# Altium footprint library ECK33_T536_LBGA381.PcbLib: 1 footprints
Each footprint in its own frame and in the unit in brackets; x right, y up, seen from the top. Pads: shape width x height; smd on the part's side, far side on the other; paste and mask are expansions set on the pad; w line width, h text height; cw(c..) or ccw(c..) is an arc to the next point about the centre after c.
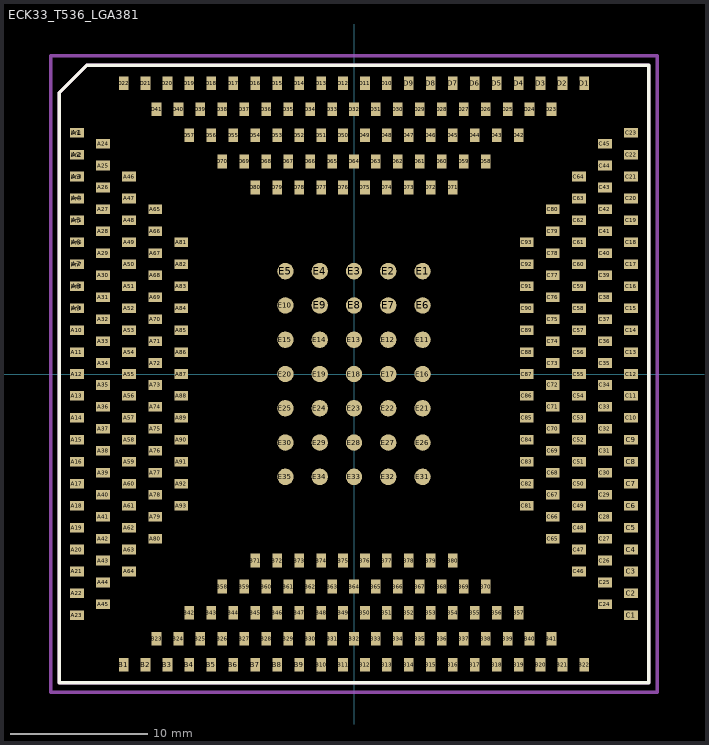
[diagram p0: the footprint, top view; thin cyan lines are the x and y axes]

## ECK33_T536_LGA381 [mm]
pads (727):
  rect 1x0.7 smd: A1(-20.2,17.6) A2(-20.2,16) A3(-20.2,14.4) A4(-20.2,12.8) A5(-20.2,11.2) A6(-20.2,9.6) A7(-20.2,8) A8(-20.2,6.4) A9(-20.2,4.8) A10(-20.2,3.2) A11(-20.2,1.6) A12(-20.2,0) A13(-20.2,-1.6) A14(-20.2,-3.2) A15(-20.2,-4.8) A16(-20.2,-6.4) A17(-20.2,-8) A18(-20.2,-9.6) A19(-20.2,-11.2) A20(-20.2,-12.8) A21(-20.2,-14.4) A22(-20.2,-16) A23(-20.2,-17.6) A24(-18.3,16.8) A25(-18.3,15.2) A26(-18.3,13.6) A27(-18.3,12) A28(-18.3,10.4) A29(-18.3,8.8) A30(-18.3,7.2) A31(-18.3,5.6) A32(-18.3,4) A33(-18.3,2.4) A34(-18.3,0.8) A35(-18.3,-0.8) A36(-18.3,-2.4) A37(-18.3,-4) A38(-18.3,-5.6) A39(-18.3,-7.2) A40(-18.3,-8.8) A41(-18.3,-10.4) A42(-18.3,-12) A43(-18.3,-13.6) A44(-18.3,-15.2) A45(-18.3,-16.8) A46(-16.4,14.4) A47(-16.4,12.8) A48(-16.4,11.2) A49(-16.4,9.6) A50(-16.4,8) A51(-16.4,6.4) A52(-16.4,4.8) A53(-16.4,3.2) A54(-16.4,1.6) A55(-16.4,0) A56(-16.4,-1.6) A57(-16.4,-3.2) A58(-16.4,-4.8) A59(-16.4,-6.4) A60(-16.4,-8) A61(-16.4,-9.6) A62(-16.4,-11.2) A63(-16.4,-12.8) A64(-16.4,-14.4) A65(-14.5,12) A66(-14.5,10.4) A67(-14.5,8.8) A68(-14.5,7.2) A69(-14.5,5.6) A70(-14.5,4) A71(-14.5,2.4) A72(-14.5,0.8) A73(-14.5,-0.8) A74(-14.5,-2.4) A75(-14.5,-4) A76(-14.5,-5.6) A77(-14.5,-7.2) A78(-14.5,-8.8) A79(-14.5,-10.4) A80(-14.5,-12) A81(-12.6,9.6) A82(-12.6,8) A83(-12.6,6.4) A84(-12.6,4.8) A85(-12.6,3.2) A86(-12.6,1.6) A87(-12.6,0) A88(-12.6,-1.6) A89(-12.6,-3.2) A90(-12.6,-4.8) A91(-12.6,-6.4) A92(-12.6,-8) A93(-12.6,-9.6) C1(20.2,-17.6) C2(20.2,-16) C3(20.2,-14.4) C4(20.2,-12.8) C5(20.2,-11.2) C6(20.2,-9.6) C7(20.2,-8) C8(20.2,-6.4) C9(20.2,-4.8) C10(20.2,-3.2) C11(20.2,-1.6) C12(20.2,0) C13(20.2,1.6) C14(20.2,3.2) C15(20.2,4.8) C16(20.2,6.4) C17(20.2,8) C18(20.2,9.6) C19(20.2,11.2) C20(20.2,12.8) C21(20.2,14.4) C22(20.2,16) C23(20.2,17.6) C24(18.3,-16.8) C25(18.3,-15.2) C26(18.3,-13.6) C27(18.3,-12) C28(18.3,-10.4) C29(18.3,-8.8) C30(18.3,-7.2) C31(18.3,-5.6) C32(18.3,-4) C33(18.3,-2.4) C34(18.3,-0.8) C35(18.3,0.8) C36(18.3,2.4) C37(18.3,4) C38(18.3,5.6) C39(18.3,7.2) C40(18.3,8.8) C41(18.3,10.4) C42(18.3,12) C43(18.3,13.6) C44(18.3,15.2) C45(18.3,16.8) C46(16.4,-14.4) C47(16.4,-12.8) C48(16.4,-11.2) C49(16.4,-9.6) C50(16.4,-8) C51(16.4,-6.4) C52(16.4,-4.8) C53(16.4,-3.2) C54(16.4,-1.6) C55(16.4,0) C56(16.4,1.6) C57(16.4,3.2) C58(16.4,4.8) C59(16.4,6.4) C60(16.4,8) C61(16.4,9.6) C62(16.4,11.2) C63(16.4,12.8) C64(16.4,14.4) C65(14.5,-12) C66(14.5,-10.4) C67(14.5,-8.8) C68(14.5,-7.2) C69(14.5,-5.6) C70(14.5,-4) C71(14.5,-2.4) C72(14.5,-0.8) C73(14.5,0.8) C74(14.5,2.4) C75(14.5,4) C76(14.5,5.6) C77(14.5,7.2) C78(14.5,8.8) C79(14.5,10.4) C80(14.5,12) C81(12.6,-9.6) C82(12.6,-8) C83(12.6,-6.4) C84(12.6,-4.8) C85(12.6,-3.2) C86(12.6,-1.6) C87(12.6,0) C88(12.6,1.6) C89(12.6,3.2) C90(12.6,4.8) C91(12.6,6.4) C92(12.6,8) C93(12.6,9.6)
  rect 0.7x1 smd: B1(-16.8,-21.2) B2(-15.2,-21.2) B3(-13.6,-21.2) B4(-12,-21.2) B5(-10.4,-21.2) B6(-8.8,-21.2) B7(-7.2,-21.2) B8(-5.6,-21.2) B9(-4,-21.2) B10(-2.4,-21.2) B11(-0.8,-21.2) B12(0.8,-21.2) B13(2.4,-21.2) B14(4,-21.2) B15(5.6,-21.2) B16(7.2,-21.2) B17(8.8,-21.2) B18(10.4,-21.2) B19(12,-21.2) B20(13.6,-21.2) B21(15.2,-21.2) B22(16.8,-21.2) B23(-14.4,-19.3) B24(-12.8,-19.3) B25(-11.2,-19.3) B26(-9.6,-19.3) B27(-8,-19.3) B28(-6.4,-19.3) B29(-4.8,-19.3) B30(-3.2,-19.3) B31(-1.6,-19.3) B32(0,-19.3) B33(1.6,-19.3) B34(3.2,-19.3) B35(4.8,-19.3) B36(6.4,-19.3) B37(8,-19.3) B38(9.6,-19.3) B39(11.2,-19.3) B40(12.8,-19.3) B41(14.4,-19.3) B42(-12,-17.4) B43(-10.4,-17.4) B44(-8.8,-17.4) B45(-7.2,-17.4) B46(-5.6,-17.4) B47(-4,-17.4) B48(-2.4,-17.4) B49(-0.8,-17.4) B50(0.8,-17.4) B51(2.4,-17.4) B52(4,-17.4) B53(5.6,-17.4) B54(7.2,-17.4) B55(8.8,-17.4) B56(10.4,-17.4) B57(12,-17.4) B58(-9.6,-15.5) B59(-8,-15.5) B60(-6.4,-15.5) B61(-4.8,-15.5) B62(-3.2,-15.5) B63(-1.6,-15.5) B64(0,-15.5) B65(1.6,-15.5) B66(3.2,-15.5) B67(4.8,-15.5) B68(6.4,-15.5) B69(8,-15.5) B70(9.6,-15.5) B71(-7.2,-13.6) B72(-5.6,-13.6) B73(-4,-13.6) B74(-2.4,-13.6) B75(-0.8,-13.6) B76(0.8,-13.6) B77(2.4,-13.6) B78(4,-13.6) B79(5.6,-13.6) B80(7.2,-13.6) D1(16.8,21.2) D2(15.2,21.2) D3(13.6,21.2) D4(12,21.2) D5(10.4,21.2) D6(8.8,21.2) D7(7.2,21.2) D8(5.6,21.2) D9(4,21.2) D10(2.4,21.2) D11(0.8,21.2) D12(-0.8,21.2) D13(-2.4,21.2) D14(-4,21.2) D15(-5.6,21.2) D16(-7.2,21.2) D17(-8.8,21.2) D18(-10.4,21.2) D19(-12,21.2) D20(-13.6,21.2) D21(-15.2,21.2) D22(-16.8,21.2) D23(14.4,19.3) D24(12.8,19.3) D25(11.2,19.3) D26(9.6,19.3) D27(8,19.3) D28(6.4,19.3) D29(4.8,19.3) D30(3.2,19.3) D31(1.6,19.3) D32(0,19.3) D33(-1.6,19.3) D34(-3.2,19.3) D35(-4.8,19.3) D36(-6.4,19.3) D37(-8,19.3) D38(-9.6,19.3) D39(-11.2,19.3) D40(-12.8,19.3) D41(-14.4,19.3) D42(12,17.4) D43(10.4,17.4) D44(8.8,17.4) D45(7.2,17.4) D46(5.6,17.4) D47(4,17.4) D48(2.4,17.4) D49(0.8,17.4) D50(-0.8,17.4) D51(-2.4,17.4) D52(-4,17.4) D53(-5.6,17.4) D54(-7.2,17.4) D55(-8.8,17.4) D56(-10.4,17.4) D57(-12,17.4) D58(9.6,15.5) D59(8,15.5) D60(6.4,15.5) D61(4.8,15.5) D62(3.2,15.5) D63(1.6,15.5) D64(0,15.5) D65(-1.6,15.5) D66(-3.2,15.5) D67(-4.8,15.5) D68(-6.4,15.5) D69(-8,15.5) D70(-9.6,15.5) D71(7.2,13.6) D72(5.6,13.6) D73(4,13.6) D74(2.4,13.6) D75(0.8,13.6) D76(-0.8,13.6) D77(-2.4,13.6) D78(-4,13.6) D79(-5.6,13.6) D80(-7.2,13.6)
  round 1.2 smd: E1(5,7.5) E2(2.5,7.5) E3(0,7.5) E4(-2.5,7.5) E5(-5,7.5) E6(5,5) E7(2.5,5) E8(0,5) E9(-2.5,5) E10(-5,5) E11(5,2.5) E12(2.5,2.5) E13(0,2.5) E14(-2.5,2.5) E15(-5,2.5) E16(5,0) E17(2.5,0) E18(0,0) E19(-2.5,0) E20(-5,0) E21(5,-2.5) E22(2.5,-2.5) E23(0,-2.5) E24(-2.5,-2.5) E25(-5,-2.5) E26(5,-5) E27(2.5,-5) E28(0,-5) E29(-2.5,-5) E30(-5,-5) E31(5,-7.5) E32(2.5,-7.5) E33(0,-7.5) E34(-2.5,-7.5) E35(-5,-7.5)
  rrect25% 1x0.7 on Top Paste: Un1(-20.2,17.6) Un2(-20.2,16) Un3(-20.2,14.4) Un4(-20.2,12.8) Un5(-20.2,11.2) Un6(-20.2,9.6) Un7(-20.2,8) Un8(-20.2,6.4) Un9(-20.2,4.8) Un10(-20.2,3.2) Un11(-20.2,1.6) Un12(-20.2,0) Un13(-20.2,-1.6) Un14(-20.2,-3.2) Un15(-20.2,-4.8) Un16(-20.2,-6.4) Un17(-20.2,-8) Un18(-20.2,-9.6) Un19(-20.2,-11.2) Un20(-20.2,-12.8) Un21(-20.2,-14.4) Un22(-20.2,-16) Un23(-20.2,-17.6) Un24(-18.3,16.8) Un25(-18.3,15.2) Un26(-18.3,13.6) Un27(-18.3,12) Un28(-18.3,10.4) Un29(-18.3,8.8) Un30(-18.3,7.2) Un31(-18.3,5.6) Un32(-18.3,4) Un33(-18.3,2.4) Un34(-18.3,0.8) Un35(-18.3,-0.8) Un36(-18.3,-2.4) Un37(-18.3,-4) Un38(-18.3,-5.6) Un39(-18.3,-7.2) Un40(-18.3,-8.8) Un41(-18.3,-10.4) Un42(-18.3,-12) Un43(-18.3,-13.6) Un44(-18.3,-15.2) Un45(-18.3,-16.8) Un48(-16.4,14.4) Un49(-16.4,12.8) Un50(-16.4,11.2) Un51(-16.4,9.6) Un52(-16.4,8) Un53(-16.4,6.4) Un54(-16.4,4.8) Un55(-16.4,3.2) Un56(-16.4,1.6) Un57(-16.4,0) Un58(-16.4,-1.6) Un59(-16.4,-3.2) Un60(-16.4,-4.8) Un61(-16.4,-6.4) Un62(-16.4,-8) Un63(-16.4,-9.6) Un64(-16.4,-11.2) Un65(-16.4,-12.8) Un66(-16.4,-14.4) Un69(-14.5,12) Un70(-14.5,10.4) Un71(-14.5,8.8) Un72(-14.5,7.2) Un73(-14.5,5.6) Un74(-14.5,4) Un75(-14.5,2.4) Un76(-14.5,0.8) Un77(-14.5,-0.8) Un78(-14.5,-2.4) Un79(-14.5,-4) Un80(-14.5,-5.6) Un81(-14.5,-7.2) Un82(-14.5,-8.8) Un83(-14.5,-10.4) Un84(-14.5,-12) Un91(-12.6,9.6) Un92(-12.6,8) Un93(-12.6,6.4) Un94(-12.6,4.8) Un95(-12.6,3.2) Un96(-12.6,1.6) Un97(-12.6,0) Un98(-12.6,-1.6) Un99(-12.6,-3.2) Un100(-12.6,-4.8) Un101(-12.6,-6.4) Un102(-12.6,-8) Un103(-12.6,-9.6) Un244(12.6,9.6) Un245(12.6,8) Un246(12.6,6.4) Un247(12.6,4.8) Un248(12.6,3.2) Un249(12.6,1.6) Un250(12.6,0) Un251(12.6,-1.6) Un252(12.6,-3.2) Un253(12.6,-4.8) Un254(12.6,-6.4) Un255(12.6,-8) Un256(12.6,-9.6) Un263(14.5,12) Un264(14.5,10.4) Un265(14.5,8.8) Un266(14.5,7.2) Un267(14.5,5.6) Un268(14.5,4) Un269(14.5,2.4) Un270(14.5,0.8) Un271(14.5,-0.8) Un272(14.5,-2.4) Un273(14.5,-4) Un274(14.5,-5.6) Un275(14.5,-7.2) Un276(14.5,-8.8) Un277(14.5,-10.4) Un278(14.5,-12) Un281(16.4,14.4) Un282(16.4,12.8) Un283(16.4,11.2) Un284(16.4,9.6) Un285(16.4,8) Un286(16.4,6.4) Un287(16.4,4.8) Un288(16.4,3.2) Un289(16.4,1.6) Un290(16.4,0) Un291(16.4,-1.6) Un292(16.4,-3.2) Un293(16.4,-4.8) Un294(16.4,-6.4) Un295(16.4,-8) Un296(16.4,-9.6) Un297(16.4,-11.2) Un298(16.4,-12.8) Un299(16.4,-14.4) Un302(18.3,16.8) Un303(18.3,15.2) Un304(18.3,13.6) Un305(18.3,12) Un306(18.3,10.4) Un307(18.3,8.8) Un308(18.3,7.2) Un309(18.3,5.6) Un310(18.3,4) Un311(18.3,2.4) Un312(18.3,0.8) Un313(18.3,-0.8) Un314(18.3,-2.4) Un315(18.3,-4) Un316(18.3,-5.6) Un317(18.3,-7.2) Un318(18.3,-8.8) Un319(18.3,-10.4) Un320(18.3,-12) Un321(18.3,-13.6) Un322(18.3,-15.2) Un323(18.3,-16.8) Un324(20.2,17.6) Un325(20.2,16) Un326(20.2,14.4) Un327(20.2,12.8) Un328(20.2,11.2) Un329(20.2,9.6) Un330(20.2,8) Un331(20.2,6.4) Un332(20.2,4.8) Un333(20.2,3.2) Un334(20.2,1.6) Un335(20.2,0) Un336(20.2,-1.6) Un337(20.2,-3.2) Un338(20.2,-4.8) Un339(20.2,-6.4) Un340(20.2,-8) Un341(20.2,-9.6) Un342(20.2,-11.2) Un343(20.2,-12.8) Un344(20.2,-14.4) Un345(20.2,-16) Un346(20.2,-17.6)
  rrect25% 0.7x1 on Top Paste: Un46(-16.8,21.2) Un47(-16.8,-21.2) Un67(-15.2,21.2) Un68(-15.2,-21.2) Un85(-14.4,19.3) Un86(-14.4,-19.3) Un87(-13.6,21.2) Un88(-13.6,-21.2) Un89(-12.8,19.3) Un90(-12.8,-19.3) Un104(-12,21.2) Un105(-12,17.4) Un106(-12,-17.4) Un107(-12,-21.2) Un108(-11.2,19.3) Un109(-11.2,-19.3) Un110(-10.4,21.2) Un111(-10.4,17.4) Un112(-10.4,-17.4) Un113(-10.4,-21.2) Un114(-9.6,19.3) Un115(-9.6,15.5) Un116(-9.6,-15.5) Un117(-9.6,-19.3) Un118(-8.8,21.2) Un119(-8.8,17.4) Un120(-8.8,-17.4) Un121(-8.8,-21.2) Un122(-8,19.3) Un123(-8,15.5) Un124(-8,-15.5) Un125(-8,-19.3) Un126(-7.2,21.2) Un127(-7.2,17.4) Un128(-7.2,13.6) Un129(-7.2,-13.6) Un130(-7.2,-17.4) Un131(-7.2,-21.2) Un132(-6.4,19.3) Un133(-6.4,15.5) Un134(-6.4,-15.5) Un135(-6.4,-19.3) Un136(-5.6,21.2) Un137(-5.6,17.4) Un138(-5.6,13.6) Un139(-5.6,-13.6) Un140(-5.6,-17.4) Un141(-5.6,-21.2) Un142(-4.8,19.3) Un143(-4.8,15.5) Un144(-4.8,-15.5) Un145(-4.8,-19.3) Un146(-4,21.2) Un147(-4,17.4) Un148(-4,13.6) Un149(-4,-13.6) Un150(-4,-17.4) Un151(-4,-21.2) Un152(-3.2,19.3) Un153(-3.2,15.5) Un154(-3.2,-15.5) Un155(-3.2,-19.3) Un156(-2.4,21.2) Un157(-2.4,17.4) Un158(-2.4,13.6) Un159(-2.4,-13.6) Un160(-2.4,-17.4) Un161(-2.4,-21.2) Un162(-1.6,19.3) Un163(-1.6,15.5) Un164(-1.6,-15.5) Un165(-1.6,-19.3) Un166(-0.8,21.2) Un167(-0.8,17.4) Un168(-0.8,13.6) Un169(-0.8,-13.6) Un170(-0.8,-17.4) Un171(-0.8,-21.2) Un172(0,19.3) Un173(0,15.5) Un174(0,-15.5) Un175(0,-19.3) Un176(0.8,21.2) Un177(0.8,17.4) Un178(0.8,13.6) Un179(0.8,-13.6) Un180(0.8,-17.4) Un181(0.8,-21.2) Un182(1.6,19.3) Un183(1.6,15.5) Un184(1.6,-15.5) Un185(1.6,-19.3) Un186(2.4,21.2) Un187(2.4,17.4) Un188(2.4,13.6) Un189(2.4,-13.6) Un190(2.4,-17.4) Un191(2.4,-21.2) Un192(3.2,19.3) Un193(3.2,15.5) Un194(3.2,-15.5) Un195(3.2,-19.3) Un196(4,21.2) Un197(4,17.4) Un198(4,13.6) Un199(4,-13.6) Un200(4,-17.4) Un201(4,-21.2) Un202(4.8,19.3) Un203(4.8,15.5) Un204(4.8,-15.5) Un205(4.8,-19.3) Un206(5.6,21.2) Un207(5.6,17.4) Un208(5.6,13.6) Un209(5.6,-13.6) Un210(5.6,-17.4) Un211(5.6,-21.2) Un212(6.4,19.3) Un213(6.4,15.5) Un214(6.4,-15.5) Un215(6.4,-19.3) Un216(7.2,21.2) Un217(7.2,17.4) Un218(7.2,13.6) Un219(7.2,-13.6) Un220(7.2,-17.4) Un221(7.2,-21.2) Un222(8,19.3) Un223(8,15.5) Un224(8,-15.5) Un225(8,-19.3) Un226(8.8,21.2) Un227(8.8,17.4) Un228(8.8,-17.4) Un229(8.8,-21.2) Un230(9.6,19.3) Un231(9.6,15.5) Un232(9.6,-15.5) Un233(9.6,-19.3) Un234(10.4,21.2) Un235(10.4,17.4) Un236(10.4,-17.4) Un237(10.4,-21.2) Un238(11.2,19.3) Un239(11.2,-19.3) Un240(12,21.2) Un241(12,17.4) Un242(12,-17.4) Un243(12,-21.2) Un257(12.8,19.3) Un258(12.8,-19.3) Un259(13.6,21.2) Un260(13.6,-21.2) Un261(14.4,19.3) Un262(14.4,-19.3) Un279(15.2,21.2) Un280(15.2,-21.2) Un300(16.8,21.2) Un301(16.8,-21.2)
F.SilkS:
  lines w0.254: -21.5,-22.5 -21.5,20.5 -19.5,22.5 21.5,22.5 21.5,-22.5 -21.5,-22.5
F.CrtYd:
  lines w0.254: -22.1,-23.2 -22.1,23.2 22.1,23.2 22.1,-23.2 -22.1,-23.2
F.Fab:
  lines w0.254: -21.5,-22.5 -21.5,20.5 -19.5,22.5 21.5,22.5 21.5,-22.5 -21.5,-22.5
